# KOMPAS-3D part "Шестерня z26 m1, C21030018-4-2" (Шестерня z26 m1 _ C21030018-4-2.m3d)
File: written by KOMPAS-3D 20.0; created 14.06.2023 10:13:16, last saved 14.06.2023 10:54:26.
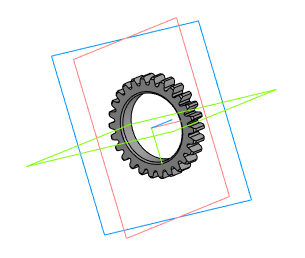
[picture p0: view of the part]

Document properties: Автор: user; Полное имя файла: C:\Users\kosenko.ky\Desktop\Шестерня z26 m1 _ C21030018-4-2.m3d

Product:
- Part/product: Шестерня z26 m1  | designation C21030018-4-2
    Материал: Сталь 40Х  ГОСТ 4543-2016 (density 7850 kg/m3)
    Масса: 0.00931038
    source file: Шестерня z26 m1 _ C21030018-4-2.cdw

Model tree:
1. Эскиз:1
2. Элемент выдавливания:1
     Расстояние 1 = 5
3. Фаска:1  (with: Элемент выдавливания:1)
     Угол = 45; Длина 1 = 0.5; Длина 2 = 0.5
4. Фаска:2  (with: Элемент выдавливания:1)
     Угол = 45; Длина 1 = 0.5; Длина 2 = 0.5
5. Эскиз:2  (with: Элемент выдавливания:1, Фаска:2)
6. Элемент выдавливания:3  (labels: Сталь 40Х  ГОСТ 4543-2016)
     Расстояние 2 = 10

Expressions: C21030018-4-2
